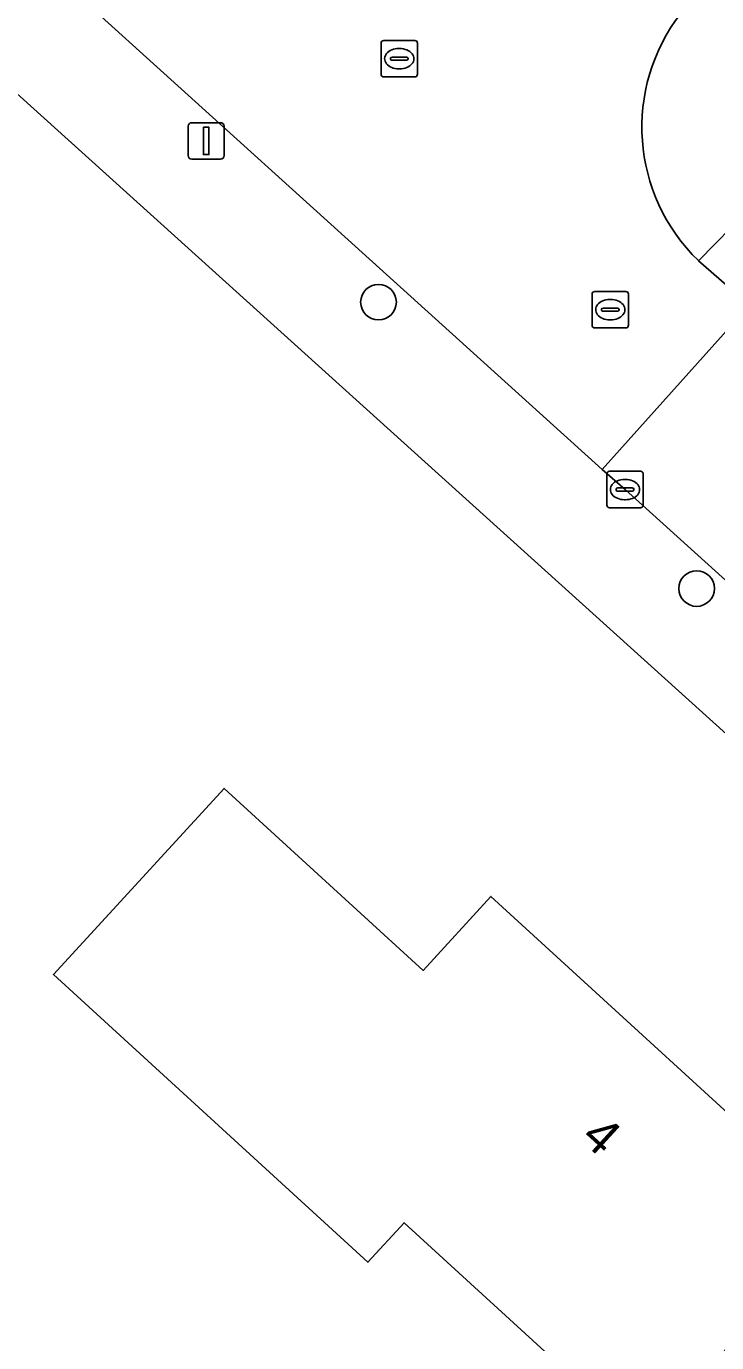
# Model space of a CAD drawing. Extents: x 163266 to 164362, y 381528 to 382286.
# Drawn here: x 164010.63 to 164029.55, y 381952.84 to 381988.97 of the extents above; entities that cross this region are included whole.
import ezdxf

# ---------------------------------------------------------------- set-up
doc = ezdxf.new("R2010")
doc.units = 0
for name, color, linetype in [('IMGEO_Berm_groen', 7, 'Continuous'), ('IMGEO_Boom', 7, 'Continuous'), ('IMGEO_Erf', 7, 'Continuous'), ('IMGEO_Kolk', 7, 'Continuous'), ('IMGEO_Lichtmast', 7, 'Continuous'), ('IMGEO_Pand', 7, 'Continuous'), ('IMGEO_Pand_nummerreeks', 7, 'Continuous'), ('IMGEO_Rijbaan_lokaal_gesloten', 7, 'Continuous'), ('IMGEO_Rijbaan_lokaal_open', 7, 'Continuous'), ('IMGEO_Rioolput', 7, 'Continuous'), ('IMGEO_Voetpad_open', 7, 'Continuous')]:
    doc.layers.add(name, color=color, linetype=linetype)

msp = doc.modelspace()

# ---------------------------------------------------------------- linework, layer by layer
at = {"layer": 'IMGEO_Berm_groen'}
msp.add_lwpolyline([(164042.219, 381973.377), (164037.134, 381977.811), (164034.627, 381980.081), (164030.413, 381983.927), (164029.055, 381982.538), (164030.451, 381981.319), (164031.197, 381980.639), (164037.747, 381974.712), (164038.888, 381973.716)], dxfattribs=at)
at = {"layer": 'IMGEO_Boom'}
for centre in [(164020.282, 381981.399), (164029.005, 381973.54)]:
    msp.add_circle(centre, 0.489, dxfattribs=at)
at = {"layer": 'IMGEO_Erf'}
msp.add_lwpolyline([(163981.759, 381896.51), (163982.978, 381897.576), (163983.903, 381898.385), (164000, 381912.621), (164013.095, 381923.126), (164045.138, 381950.831), (164045.957, 381951.785), (164047.495, 381953.575), (164005.841, 381991.21), (164000, 381996.499), (163996.133, 382000), (163967.622, 382025.804), (163959.22, 382032.884), (163952.437, 382038.271), (163951.112, 382039.278), (163945.397, 382043.624), (163945.352, 382043.639), (163943.77, 382044.161)], dxfattribs=at)
msp.add_lwpolyline([(164020.984, 381956.134), (164019.991, 381955.05), (164011.368, 381962.945), (164016.048, 381968.057), (164021.504, 381963.061), (164023.365, 381965.093), (164033.058, 381956.218), (164027.51, 381950.159)], close=True, dxfattribs=at)
at = {"layer": 'IMGEO_Kolk'}
for p, q in [((164026.54, 381975.831), (164026.54, 381976.683)), ((164026.615, 381976.757), (164027.467, 381976.757)), ((164027.541, 381976.683), (164027.541, 381975.831)), ((164026.799, 381976.251), (164026.799, 381976.263)), ((164026.842, 381976.3), (164027.24, 381976.3)), ((164027.028, 381976.537), (164027.053, 381976.537)), ((164027.283, 381976.263), (164027.283, 381976.251)), ((164027.237, 381976.214), (164026.839, 381976.214)), ((164027.051, 381975.977), (164027.026, 381975.977)), ((164027.467, 381975.757), (164026.615, 381975.757))]:
    msp.add_line(p, q, dxfattribs=at)
for points in [[(164026.54, 381975.831), (164026.54, 381976.683)], [(164026.615, 381976.757), (164027.467, 381976.757)], [(164027.541, 381976.683), (164027.541, 381975.831)], [(164027.467, 381975.757), (164026.615, 381975.757)]]:
    msp.add_lwpolyline(points, dxfattribs=at)
for centre, radius, start, end in [((164026.617, 381976.681), 0.0765, 91.552, 178.448), ((164026.617, 381976.681), 0.0765, 91.552, 178.448), ((164027.465, 381976.681), 0.0765, 1.552, 88.448), ((164027.465, 381976.681), 0.0765, 1.552, 88.448), ((164026.839, 381976.26), 0.0403, 85.8775, 175.7526), ((164026.836, 381976.25), 0.0366, 178.938, 274.7102), ((164027.24, 381976.257), 0.043, 264.8664, 352.4533), ((164027.244, 381976.262), 0.0386, 1.7309, 96.639), ((164026.617, 381975.833), 0.0765, 181.552, 268.448), ((164026.617, 381975.833), 0.0765, 181.552, 268.448), ((164027.465, 381975.833), 0.0765, 271.552, 358.448), ((164027.465, 381975.833), 0.0765, 271.552, 358.448)]:
    msp.add_arc(centre, radius, start, end, dxfattribs=at)
for centre, major_axis, ratio, start_param, end_param in [((164027.027, 381976.257), (-0.387, 0.002), 0.722429, 4.712389, 7.853982), ((164027.052, 381976.257), (-0.39, 0.002), 0.717154, 1.570796, 4.712389)]:
    msp.add_ellipse(centre, major_axis=major_axis, ratio=ratio, start_param=start_param, end_param=end_param, dxfattribs=at)
at = {"layer": 'IMGEO_Lichtmast'}
for p, q in [((164015.061, 381985.425), (164015.061, 381986.225)), ((164015.061, 381986.225), (164015.061, 381985.425)), ((164015.161, 381986.325), (164015.951, 381986.325)), ((164015.951, 381986.325), (164015.161, 381986.325)), ((164016.051, 381986.225), (164016.051, 381985.425)), ((164016.051, 381985.425), (164016.051, 381986.225)), ((164015.951, 381985.325), (164015.161, 381985.325)), ((164015.161, 381985.325), (164015.951, 381985.325))]:
    msp.add_line(p, q, dxfattribs=at)
msp.add_lwpolyline([(164015.481, 381986.2), (164015.631, 381986.2), (164015.631, 381985.45), (164015.481, 381985.45), (164015.481, 381986.2)], dxfattribs=at)
for centre, start, end in [((164015.161, 381986.225), 90, 180), ((164015.161, 381986.225), 90, 180), ((164015.951, 381986.225), 0, 90), ((164015.951, 381986.225), 360, 90), ((164015.161, 381985.425), 180, 270), ((164015.161, 381985.425), 180, 270), ((164015.951, 381985.425), 270, 0), ((164015.951, 381985.425), 270, 0)]:
    msp.add_arc(centre, 0.1, start, end, dxfattribs=at)
at = {"layer": 'IMGEO_Pand'}
msp.add_lwpolyline([(164027.51, 381950.159), (164033.058, 381956.218), (164023.365, 381965.093), (164021.504, 381963.061), (164016.048, 381968.057), (164011.368, 381962.945), (164019.991, 381955.05), (164020.984, 381956.134)], close=True, dxfattribs=at)
at = {"layer": 'IMGEO_Rijbaan_lokaal_gesloten'}
msp.add_lwpolyline([(164038.888, 381973.716), (164037.747, 381974.712), (164031.197, 381980.639), (164030.451, 381981.319), (164026.418, 381976.805), (164027.042, 381976.258), (164032.457, 381971.363), (164033.656, 381970.307), (164034.847, 381969.281), (164042.682, 381962.727), (164044.634, 381961.153), (164048.239, 381958.16), (164050.944, 381955.945)], dxfattribs=at)
at = {"layer": 'IMGEO_Rijbaan_lokaal_open'}
msp.add_lwpolyline([(164018.578, 381992.02), (164017.12, 381993.339), (164017.02, 381993.429), (164015.617, 381994.711), (164011.535, 381990.277), (164026.418, 381976.805), (164030.451, 381981.319), (164029.055, 381982.538)], dxfattribs=at)
msp.add_arc((164032.608, 381986.204), 5.105, 142.3155, 225.8929, dxfattribs=at)
at = {"layer": 'IMGEO_Rioolput'}
for p, q in [((164020.351, 381987.654), (164020.351, 381988.506)), ((164020.426, 381988.58), (164021.278, 381988.58)), ((164021.352, 381988.506), (164021.352, 381987.654)), ((164020.839, 381988.36), (164020.864, 381988.36)), ((164020.61, 381988.074), (164020.61, 381988.086)), ((164021.048, 381988.037), (164020.65, 381988.037)), ((164020.653, 381988.123), (164021.051, 381988.123)), ((164020.862, 381987.8), (164020.837, 381987.8)), ((164021.094, 381988.086), (164021.094, 381988.074)), ((164021.278, 381987.58), (164020.426, 381987.58)), ((164026.211, 381981.693), (164027.063, 381981.693)), ((164026.136, 381980.767), (164026.136, 381981.619)), ((164026.624, 381981.473), (164026.649, 381981.473)), ((164027.137, 381981.619), (164027.137, 381980.767)), ((164026.395, 381981.187), (164026.395, 381981.199)), ((164026.833, 381981.15), (164026.435, 381981.15)), ((164026.438, 381981.236), (164026.836, 381981.236)), ((164026.879, 381981.199), (164026.879, 381981.187)), ((164027.063, 381980.693), (164026.211, 381980.693)), ((164026.647, 381980.913), (164026.622, 381980.913))]:
    msp.add_line(p, q, dxfattribs=at)
for points in [[(164020.351, 381987.654), (164020.351, 381988.506)], [(164020.426, 381988.58), (164021.278, 381988.58)], [(164021.352, 381988.506), (164021.352, 381987.654)], [(164021.278, 381987.58), (164020.426, 381987.58)], [(164026.211, 381981.693), (164027.063, 381981.693)], [(164026.136, 381980.767), (164026.136, 381981.619)], [(164027.137, 381981.619), (164027.137, 381980.767)], [(164027.063, 381980.693), (164026.211, 381980.693)]]:
    msp.add_lwpolyline(points, dxfattribs=at)
for centre, radius, start, end in [((164020.428, 381988.504), 0.0765, 91.552, 178.448), ((164020.428, 381988.504), 0.0765, 91.552, 178.448), ((164021.276, 381988.504), 0.0765, 1.552, 88.448), ((164021.276, 381988.504), 0.0765, 1.552, 88.448), ((164020.65, 381988.083), 0.0403, 85.8775, 175.7526), ((164020.647, 381988.073), 0.0366, 178.938, 274.7102), ((164021.051, 381988.08), 0.043, 264.8664, 352.4533), ((164021.055, 381988.085), 0.0386, 1.7309, 96.639), ((164020.428, 381987.656), 0.0765, 181.552, 268.448), ((164020.428, 381987.656), 0.0765, 181.552, 268.448), ((164021.276, 381987.656), 0.0765, 271.552, 358.448), ((164021.276, 381987.656), 0.0765, 271.552, 358.448), ((164026.213, 381981.617), 0.0765, 91.552, 178.448), ((164026.213, 381981.617), 0.0765, 91.552, 178.448), ((164027.061, 381981.617), 0.0765, 1.552, 88.448), ((164027.061, 381981.617), 0.0765, 1.552, 88.448), ((164026.435, 381981.196), 0.0403, 85.8775, 175.7526), ((164026.432, 381981.186), 0.0366, 178.938, 274.7102), ((164026.836, 381981.193), 0.043, 264.8664, 352.4533), ((164026.84, 381981.198), 0.0386, 1.7309, 96.639), ((164026.213, 381980.769), 0.0765, 181.552, 268.448), ((164026.213, 381980.769), 0.0765, 181.552, 268.448), ((164027.061, 381980.769), 0.0765, 271.552, 358.448), ((164027.061, 381980.769), 0.0765, 271.552, 358.448)]:
    msp.add_arc(centre, radius, start, end, dxfattribs=at)
for centre, major_axis, ratio, start_param, end_param in [((164020.838, 381988.08), (-0.387, 0.002), 0.722429, 4.712389, 7.853982), ((164020.863, 381988.08), (-0.39, 0.002), 0.717154, 1.570796, 4.712389), ((164026.623, 381981.193), (-0.387, 0.002), 0.722429, 4.712389, 7.853982), ((164026.648, 381981.193), (-0.39, 0.002), 0.717154, 1.570796, 4.712389)]:
    msp.add_ellipse(centre, major_axis=major_axis, ratio=ratio, start_param=start_param, end_param=end_param, dxfattribs=at)
at = {"layer": 'IMGEO_Voetpad_open'}
for points in [[(163942.334, 382045.958), (163942.351, 382045.94), (163945.348, 382043.661), (163945.352, 382043.639), (163945.397, 382043.624), (163951.112, 382039.278), (163952.437, 382038.271), (163959.22, 382032.884), (163967.622, 382025.804), (163996.133, 382000), (164000, 381996.499), (164005.841, 381991.21), (164047.495, 381953.575), (164050.865, 381950.343), (164050.939, 381950.414)], [(164027.042, 381976.258), (164026.418, 381976.805), (164011.535, 381990.277), (163989.724, 382009.823), (163975.454, 382022.768), (163966.57, 382030.683), (163957.994, 382037.828), (163947.738, 382045.71), (163947.652, 382045.773)], [(164029.055, 381982.538), (164030.413, 381983.927)], [(164050.944, 381955.945), (164048.239, 381958.16), (164044.634, 381961.153), (164042.682, 381962.727), (164034.847, 381969.281), (164033.656, 381970.307), (164032.457, 381971.363), (164027.042, 381976.258)]]:
    msp.add_lwpolyline(points, dxfattribs=at)
msp.add_arc((164032.608, 381986.204), 5.105, 142.3155, 225.8929, dxfattribs=at)

# ---------------------------------------------------------------- texts
at = {"layer": 'IMGEO_Pand_nummerreeks'}
msp.add_text('4', height=1, rotation=317.5225, dxfattribs=at).set_placement((164025.793, 381958.422))

doc.saveas('drawing.dxf')
